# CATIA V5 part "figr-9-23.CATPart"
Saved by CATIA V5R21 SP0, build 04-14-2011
Part number: Part2
Bounding box of the stored display mesh (mm): x -72 to 72, y -80 to 90, z -20 to 41.296
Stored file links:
  D:\CATIA V5R21 E-RESOURCES\CATIA-V5R21\catia-v5r21-prt\c09-catia-v5r20-prt\c09-catia-v5r21-figr-9-23.CATPart
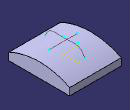
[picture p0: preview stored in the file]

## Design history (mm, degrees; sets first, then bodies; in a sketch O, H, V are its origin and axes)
Body1 (main body)
  Sketch1 on yz-plane, origin (0, 0, 0), H (0, 1, 0), V (0, 0, 1)
    arc A1 centre (5, -170) radius 190.0658 from (-80, 0) to (90, 0) cw
    point P2 (-80, 0)
    point P3 (0, 20)
    line L1 (-80, 0) -> (-80, -20)
    line L2 (-80, -20) -> (90, -20)
    line L3 (90, -20) -> (90, 0)
    coincidence: P2 H, A1 P3, P3 V
    vertical: L1 V, L3 V
    horizontal: L2 H
  Pad1: profile Sketch1, direction (1, 0, 0), length 72, mirrored extent
  Sketch2 on zx-plane, origin (0, 0, 0), H (-1, 0, 0), V (0, 0, 1)
    line L1 (-40, 30) -> (40, 30)
    horizontal: L1 H
  Sketch3 on yz-plane, origin (0, 0, 0), H (0, 1, 0), V (0, 0, 1)
    spline S1 through (60, 20) (40, 40) (10, 40) (-10, 40) (-30, 40) (-50, 20)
